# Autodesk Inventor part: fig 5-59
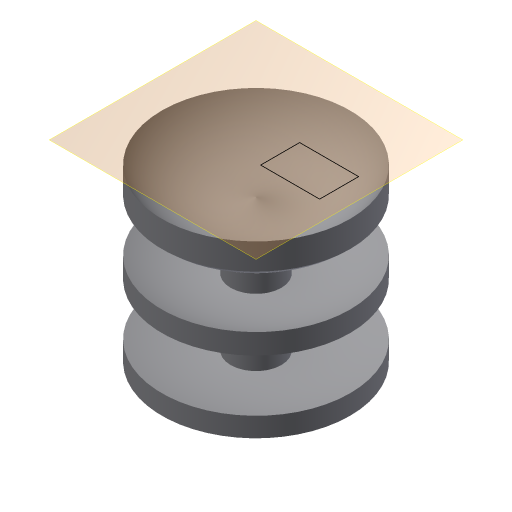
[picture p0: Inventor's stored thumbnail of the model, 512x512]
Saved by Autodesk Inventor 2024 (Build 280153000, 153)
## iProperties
Created: 2004-05
Part Number: fig 5-59
Document SubType Name: Modeling
Designer: CADCIM Technologies
Manufacturer: Standard
Standards Organization: Custom
Density: 1 g/cm^3
Material: Generic
Appearance: Default
Author: CADCIM Technologies
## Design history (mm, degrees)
sketch "Sketch1"
  geometry: L1 (0.098, 22.743)-(0.098, 0.516); L2 (-3.621, 19.305)-(-3.621, 13.061); L3 (-3.621, 10.379)-(-3.621, 3.25); L4 (-3.664, 0.516)-(0.098, 0.516); L5 (-13.694, 4.7)-(-13.694, 1.836); L6 (-13.694, 26.851)-(-13.694, 23.014); L7 (-13.694, 15.335)-(-13.694, 12.343); A1 r 10.546 centre (-4.597, 32.185) between (-13.694, 26.851) and (0.098, 22.743); A2 r 21.828 centre (-4.597, 32.185) between (-13.694, 12.343) and (-3.621, 10.379); A3 r 12.918 centre (-4.597, 32.185) between (-13.694, 23.014) and (-3.621, 19.305); A4 r 19.149 centre (-4.597, 32.185) between (-13.694, 15.335) and (-3.621, 13.061); A5 r 28.952 centre (-4.597, 32.185) between (-13.694, 4.7) and (-3.621, 3.25); A6 r 31.683 centre (-4.597, 32.185) between (-13.694, 1.836) and (-3.664, 0.516)
  constraints: 14 end point, 12 point on circle, 6 centre point, 4 perpendicular, 2 parallel, 1 vertical
revolve "Revolution1" sketch "Sketch1" stored, may be unused: angle "d0" = 90 deg
workplane "Work Plane1"
sketch "Sketch2"
  geometry: L1 (3.408, -2.846)-(12.06, -2.846); L2 (12.06, -2.846)-(12.06, 2.873); L3 (12.06, 2.873)-(3.408, 2.873); L4 (3.408, 2.873)-(3.408, -2.846)
  constraints: 8 end point, 2 parallel, 1 horizontal, 1 perpendicular
body "Solid1"
